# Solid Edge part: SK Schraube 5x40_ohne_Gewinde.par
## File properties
Author: fknapp
Template: Normal.par
Last saved by: fknapp
Revision: 26
Application: Solid Edge
Genauigkeit: 0,99
Username: fknapp
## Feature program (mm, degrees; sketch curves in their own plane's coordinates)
sketch for "unnamed RevolvedProtrusion 1" plane through (0, 0, 0) normal (0, 0, 1) x-axis (1, 0, 0)
  line (0, 40) -> (5, 40)
  line (5, 40) -> (5, 39.7)
  line (5, 39.7) -> (2.5, 37.2)
  line (2.5, 37.2) -> (2.5, 6)
  line (2.5, 6) -> (0.2, 0)
  line (0.2, 0) -> (0, 0)
  line (0, 40) -> (0, 0)
revolve "unnamed RevolvedProtrusion 1" add full turn 360 deg
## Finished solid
Body 1: solid body, 6 faces, 5 edges, 0 vertices.
  Faces by surface: cone 2, cylinder 2, plane 2
  Edges by curve: circle 5
Bounding box of the edges (mm): 10.000 x 40.000 x 10.000, from (-5, 0, -5) to (5, 40, 5).
Cylindrical faces by radius (mm): R2.5 x1, R5 x1
Conical faces (half-angle, radius in mm at the cone's reference point): 20.9735 deg R2.5 x1, 45 deg R5 x1
Planar faces by outward normal: +y 1, -y 1
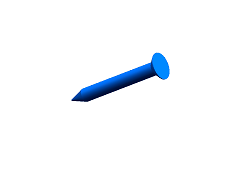
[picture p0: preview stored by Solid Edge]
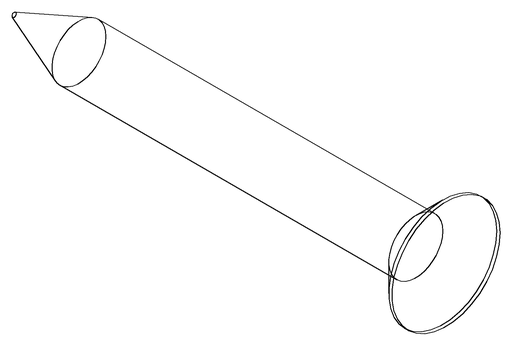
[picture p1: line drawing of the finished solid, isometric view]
